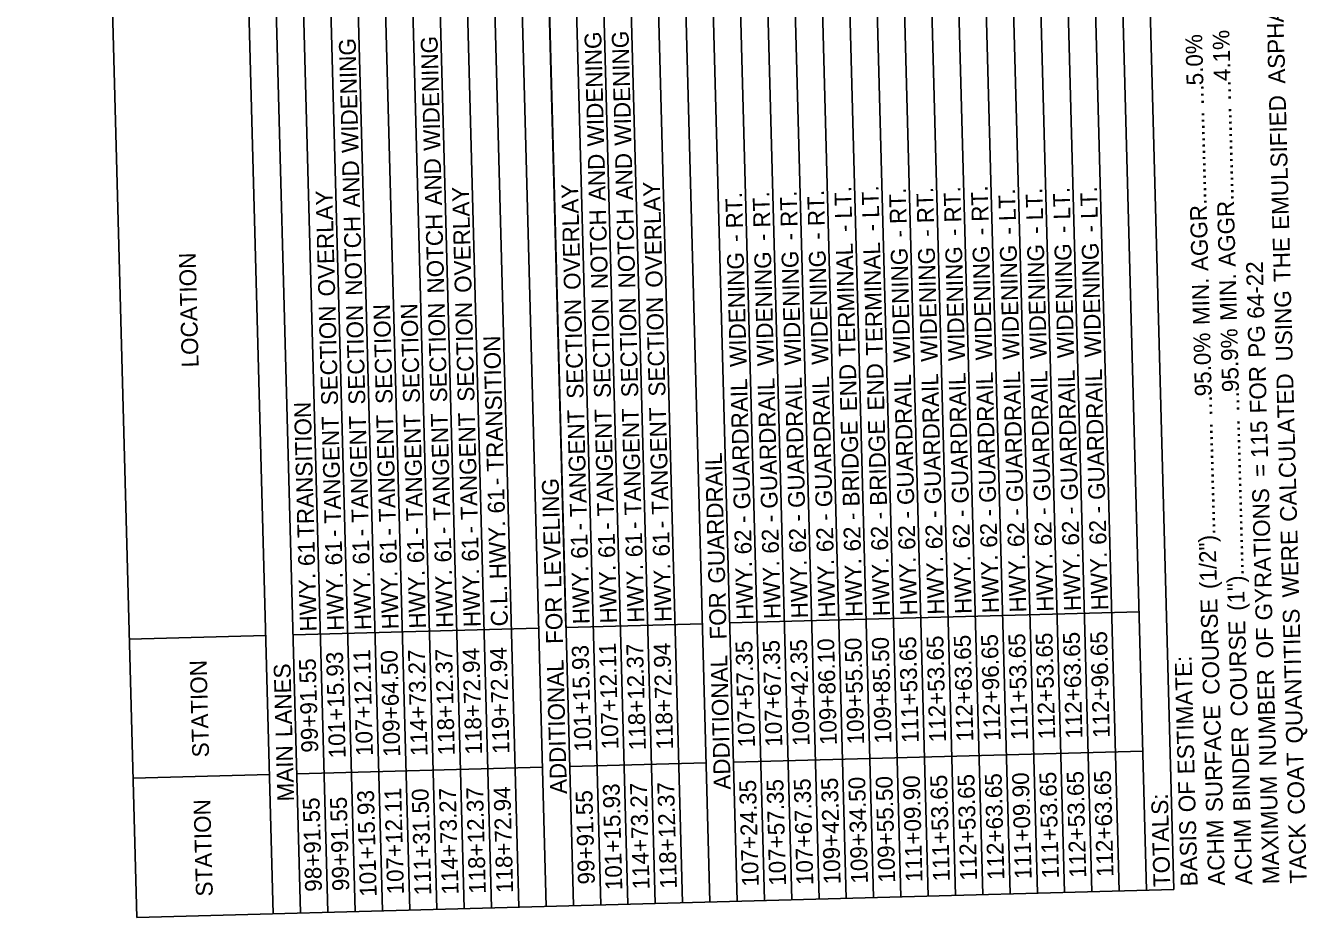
# Model space of a CAD drawing. Extents: x 1930093 to 1931323, y 596452 to 607874.
# Drawn here: x 1930485 to 1930942.8, y 603917.3 to 604235.9 of the extents above; entities that cross this region are included whole.
import ezdxf

# ---------------------------------------------------------------- set-up
doc = ezdxf.new("R2010")
doc.units = 0
doc.layers.add('Default', color=7, linetype='Continuous')

msp = doc.modelspace()

# ---------------------------------------------------------------- linework, layer by layer
at = {"layer": 'Default'}
for p, q in [((1930778.09, 603924.1), (1930738.4, 605402.65)), ((1930787.84, 603924.37), (1930748.15, 605402.91)), ((1930797.58, 603924.63), (1930757.89, 605403.17)), ((1930807.33, 603924.89), (1930767.64, 605403.43)), ((1930817.08, 603925.15), (1930777.39, 605403.69)), ((1930826.82, 603925.41), (1930787.13, 605403.95)), ((1930836.57, 603925.67), (1930796.88, 605404.22)), ((1930846.32, 603925.93), (1930806.63, 605404.48)), ((1930856.06, 603926.2), (1930816.37, 605404.74)), ((1930865.81, 603926.46), (1930826.12, 605405)), ((1930875.55, 603926.72), (1930835.86, 605405.26)), ((1930885.3, 603926.98), (1930845.61, 605405.52)), ((1930895.05, 603927.24), (1930855.36, 605405.79)), ((1930612.4, 603919.66), (1930572.71, 605398.2)), ((1930622.15, 603919.92), (1930582.46, 605398.46)), ((1930631.89, 603920.18), (1930592.2, 605398.72)), ((1930641.64, 603920.44), (1930601.95, 605398.98)), ((1930651.39, 603920.7), (1930611.7, 605399.24)), ((1930661.13, 603920.96), (1930621.44, 605399.51)), ((1930670.88, 603921.23), (1930631.19, 605399.77)), ((1930680.63, 603921.49), (1930640.93, 605400.03)), ((1930690.37, 603921.75), (1930650.68, 605400.29)), ((1930700.12, 603922.01), (1930660.43, 605400.55)), ((1930709.86, 603922.27), (1930670.17, 605400.81)), ((1930719.61, 603922.53), (1930679.92, 605401.08)), ((1930729.36, 603922.8), (1930689.67, 605401.34)), ((1930729.36, 603922.8), (1930689.67, 605401.34)), ((1930739.1, 603923.06), (1930699.41, 605401.6)), ((1930748.85, 603923.32), (1930709.16, 605401.86)), ((1930758.6, 603923.58), (1930718.91, 605402.12)), ((1930768.34, 603923.84), (1930728.65, 605402.38)), ((1930524.68, 603917.3), (1930484.99, 605395.84)), ((1930573.41, 603918.61), (1930533.72, 605397.15)), ((1930583.16, 603918.87), (1930543.47, 605397.41)), ((1930592.91, 603919.13), (1930553.22, 605397.67)), ((1930602.65, 603919.39), (1930562.96, 605397.94)), ((1930670.88, 603921.23), (1930656.54, 604455.33)), ((1930677.96, 604020.9), (1930671.62, 604256.77)), ((1930882.63, 604026.4), (1930736.44, 604022.47)), ((1930882.63, 604026.4), (1930736.44, 604022.47)), ((1930668.21, 604020.64), (1930580.49, 604018.28)), ((1930668.21, 604020.64), (1930580.49, 604018.28)), ((1930726.69, 604022.21), (1930677.96, 604020.9)), ((1930726.69, 604022.21), (1930677.96, 604020.9)), ((1930570.75, 604018.02), (1930522.01, 604016.72)), ((1930883.97, 603976.69), (1930737.77, 603972.76)), ((1930883.97, 603976.69), (1930737.77, 603972.76)), ((1930669.54, 603970.93), (1930581.83, 603968.58)), ((1930669.54, 603970.93), (1930581.83, 603968.58)), ((1930728.02, 603972.5), (1930679.29, 603971.19)), ((1930728.02, 603972.5), (1930679.29, 603971.19)), ((1930572.08, 603968.32), (1930523.35, 603967.01)), ((1930895.05, 603927.24), (1930524.68, 603917.3)), ((1930895.05, 603927.24), (1930524.68, 603917.3))]:
    msp.add_line(p, q, dxfattribs=at)

# ---------------------------------------------------------------- texts
for s, p in [(' ASPHALT', (1930934.95, 604212.93)), (' WIDENING', (1930603.99, 604188.24)), (' WIDENING', (1930633.23, 604189.02)), (' WIDENING', (1930691.71, 604190.59)), (' WIDENING', (1930701.45, 604190.86)), ('5.0%', (1930905.64, 604214.59)), ('4.1%', (1930915.35, 604216.1)), ('…', (1930905.84, 604207.19)), ('…', (1930915.55, 604208.71)), (' EMULSIFIED', (1930936.35, 604160.76)), (' AGGR...............', (1930907.48, 604146.01)), (' AGGR...............', (1930917.19, 604147.53)), (' AND', (1930692.23, 604171.02)), (' AND', (1930701.98, 604171.28)), (' AND', (1930604.51, 604168.66)), (' AND', (1930633.75, 604169.45)), (' OVERLAY', (1930595.61, 604136.96)), (' OVERLAY', (1930644.35, 604138.26)), (' OVERLAY', (1930683.33, 604139.31)), (' OVERLAY', (1930712.57, 604140.09)), (' RT.', (1930751.01, 604161.55)), (' RT.', (1930760.75, 604161.81)), (' RT.', (1930770.5, 604162.08)), (' LT.', (1930780.18, 604164.77)), (' LT.', (1930789.93, 604165.03)), (' RT.', (1930799.74, 604162.86)), (' RT.', (1930809.49, 604163.12)), (' RT.', (1930819.23, 604163.38)), (' RT.', (1930828.98, 604163.65)), (' LT.', (1930838.73, 604163.91)), (' LT.', (1930848.47, 604164.17)), (' LT.', (1930858.22, 604164.43)), (' LT.', (1930867.97, 604164.69)), (' RT.', (1930741.26, 604161.29)), (' NOTCH', (1930605.36, 604137.22)), (' NOTCH', (1930634.6, 604138)), (' NOTCH', (1930693.08, 604139.57)), (' NOTCH', (1930702.82, 604139.83)), (' -', (1930780.31, 604159.92)), (' -', (1930790.06, 604160.18)), (' -', (1930799.87, 604158.01)), (' -', (1930809.62, 604158.27)), (' -', (1930819.36, 604158.53)), (' -', (1930829.11, 604158.79)), (' -', (1930838.86, 604159.05)), (' -', (1930848.6, 604159.31)), (' -', (1930858.35, 604159.58)), (' -', (1930868.1, 604159.84)), (' -', (1930741.39, 604156.44)), (' -', (1930751.14, 604156.7)), (' -', (1930760.89, 604156.96)), (' -', (1930770.63, 604157.22)), (' TERMINAL', (1930781.5, 604115.51)), (' TERMINAL', (1930791.25, 604115.77)), (' WIDENING', (1930859.55, 604114.94)), (' WIDENING', (1930869.29, 604115.21)), (' THE', (1930936.85, 604142.12)), ('LOCATION', (1930546.79, 604113.84)), (' WIDENING', (1930742.59, 604111.8)), (' WIDENING', (1930752.34, 604112.07)), (' WIDENING', (1930762.08, 604112.33)), (' WIDENING', (1930771.83, 604112.59)), (' WIDENING', (1930801.07, 604113.37)), (' WIDENING', (1930810.82, 604113.64)), (' WIDENING', (1930820.56, 604113.9)), (' WIDENING', (1930830.31, 604114.16)), (' WIDENING', (1930840.06, 604114.42)), (' WIDENING', (1930849.8, 604114.68)), (' 64-22', (1930927.45, 604129.01)), (' MIN.', (1930908, 604126.73)), (' MIN.', (1930917.71, 604128.24)), (' USING', (1930937.61, 604113.77)), (' SECTION', (1930596.66, 604098.06)), (' SECTION', (1930606.4, 604098.32)), (' SECTION', (1930616.15, 604098.58)), (' SECTION', (1930625.9, 604098.85)), (' SECTION', (1930635.64, 604099.11)), (' SECTION', (1930645.39, 604099.37)), (' SECTION', (1930684.38, 604100.42)), (' SECTION', (1930694.12, 604100.68)), (' SECTION', (1930703.87, 604100.94)), (' SECTION', (1930713.61, 604101.2)), ('95.0%', (1930908.62, 604103.5)), ('95.9%', (1930918.34, 604105.01)), (' PG', (1930927.82, 604115.1)), (' TRANSITION', (1930655.81, 604074.39)), (' END', (1930782.03, 604095.94)), (' END', (1930791.78, 604096.2)), (' GUARDRAIL', (1930821.93, 604062.97)), (' GUARDRAIL', (1930831.68, 604063.23)), (' GUARDRAIL', (1930841.42, 604063.49)), (' GUARDRAIL', (1930851.17, 604063.76)), (' GUARDRAIL', (1930860.92, 604064.02)), (' GUARDRAIL', (1930870.66, 604064.28)), (' FOR', (1930928.35, 604095.19)), (' GUARDRAIL', (1930743.96, 604060.88)), (' GUARDRAIL', (1930753.7, 604061.14)), (' GUARDRAIL', (1930763.45, 604061.4)), (' GUARDRAIL', (1930773.2, 604061.66)), (' GUARDRAIL', (1930802.44, 604062.45)), (' GUARDRAIL', (1930812.18, 604062.71)), (' CALCULATED', (1930939.15, 604056.47)), ('…', (1930908.82, 604096.1)), ('…', (1930918.53, 604097.61)), (' TRANSITION', (1930588.17, 604050.74)), (' TANGENT', (1930685.51, 604058.21)), (' TANGENT', (1930695.25, 604058.47)), (' TANGENT', (1930705, 604058.73)), (' TANGENT', (1930714.75, 604059)), (' TANGENT', (1930597.79, 604055.86)), (' TANGENT', (1930607.54, 604056.12)), (' TANGENT', (1930617.28, 604056.38)), (' TANGENT', (1930627.03, 604056.64)), (' TANGENT', (1930636.78, 604056.9)), (' TANGENT', (1930646.52, 604057.16)), (' BRIDGE', (1930782.94, 604061.92)), (' BRIDGE', (1930792.69, 604062.19)), (' (1").........................', (1930920.49, 604024.63)), (' 115', (1930928.78, 604079.22)), (' (1/2")..................', (1930910.53, 604032.42)), (' GUARDRAIL', (1930734.92, 604034.39)), (' =', (1930928.96, 604072.47)), (' -', (1930655.94, 604069.53)), (' LEVELING', (1930676.44, 604032.82)), (' 61', (1930656.21, 604059.43)), (' GYRATIONS', (1930930.34, 604021.22)), (' -', (1930783.07, 604057.07)), (' -', (1930792.82, 604057.33)), (' -', (1930802.57, 604057.59)), (' -', (1930812.31, 604057.85)), (' -', (1930822.06, 604058.12)), (' -', (1930831.81, 604058.38)), (' -', (1930841.55, 604058.64)), (' -', (1930851.3, 604058.9)), (' -', (1930861.05, 604059.16)), (' -', (1930870.79, 604059.42)), (' -', (1930646.65, 604052.31)), (' HWY.', (1930656.84, 604035.95)), (' -', (1930685.64, 604053.36)), (' -', (1930695.38, 604053.62)), (' -', (1930705.13, 604053.88)), (' -', (1930714.88, 604054.14)), (' -', (1930744.09, 604056.02)), (' -', (1930753.83, 604056.28)), (' -', (1930763.58, 604056.55)), (' -', (1930773.33, 604056.81)), (' 62', (1930793.12, 604046.13)), (' 62', (1930802.87, 604046.39)), (' 62', (1930812.61, 604046.65)), (' 62', (1930822.36, 604046.92)), (' 62', (1930832.11, 604047.18)), (' 62', (1930841.85, 604047.44)), (' 62', (1930851.6, 604047.7)), (' 62', (1930861.35, 604047.96)), (' 62', (1930871.09, 604048.22)), (' -', (1930597.92, 604051)), (' -', (1930607.67, 604051.26)), (' -', (1930617.41, 604051.52)), (' 61', (1930627.43, 604041.68)), (' -', (1930627.16, 604051.79)), (' 61', (1930637.18, 604041.94)), (' -', (1930636.91, 604052.05)), (' 61', (1930646.92, 604042.21)), (' 61', (1930685.91, 604043.25)), (' 61', (1930695.66, 604043.51)), (' 61', (1930705.4, 604043.78)), (' 61', (1930715.15, 604044.04)), (' 62', (1930744.39, 604044.82)), (' 62', (1930754.13, 604045.08)), (' 62', (1930763.88, 604045.35)), (' 62', (1930773.63, 604045.61)), (' 62', (1930783.37, 604045.87)), (' WERE', (1930939.87, 604029.45)), (' 61', (1930588.44, 604040.64)), (' 61', (1930598.19, 604040.9)), (' 61', (1930607.94, 604041.16)), (' 61', (1930617.68, 604041.42)), ('HWY.', (1930715.72, 604022.89)), ('HWY.', (1930744.96, 604023.68)), ('HWY.', (1930754.7, 604023.94)), ('HWY.', (1930764.45, 604024.2)), ('HWY.', (1930774.2, 604024.46)), ('HWY.', (1930783.94, 604024.72)), ('HWY.', (1930793.69, 604024.98)), ('HWY.', (1930803.44, 604025.24)), ('HWY.', (1930813.18, 604025.51)), ('HWY.', (1930822.93, 604025.77)), ('HWY.', (1930832.67, 604026.03)), ('HWY.', (1930842.42, 604026.29)), ('HWY.', (1930852.17, 604026.55)), ('HWY.', (1930861.91, 604026.81)), ('HWY.', (1930871.66, 604027.08)), ('HWY.', (1930589.01, 604019.49)), ('HWY.', (1930598.76, 604019.75)), ('HWY.', (1930608.51, 604020.01)), ('HWY.', (1930618.25, 604020.27)), ('HWY.', (1930628, 604020.54)), ('HWY.', (1930637.74, 604020.8)), ('HWY.', (1930647.49, 604021.06)), ('HWY.', (1930686.48, 604022.11)), ('HWY.', (1930696.22, 604022.37)), ('HWY.', (1930705.97, 604022.63)), ('C.L.', (1930657.24, 604021.32)), (' FOR', (1930676.97, 604012.84)), (' FOR', (1930735.45, 604014.41)), (' COURSE', (1930911.54, 603994.68)), (' QUANTITIES', (1930941.27, 603977.27)), (' COURSE', (1930921.51, 603986.9)), (' OF', (1930930.7, 604007.64)), ('107+57.35', (1930745.5, 603978.08)), ('107+67.35', (1930755.25, 603978.34)), ('109+42.35', (1930765, 603978.61)), ('109+86.10', (1930774.74, 603978.9)), ('109+55.50', (1930784.49, 603979.16)), ('109+85.50', (1930794.24, 603979.42)), ('111+53.65', (1930803.98, 603979.65)), ('112+53.65', (1930813.73, 603979.91)), ('112+63.65', (1930823.48, 603980.18)), ('112+96.65', (1930833.22, 603980.44)), ('111+53.65', (1930842.97, 603980.7)), ('112+53.65', (1930852.72, 603980.96)), ('112+63.65', (1930862.46, 603981.22)), ('112+96.65', (1930872.21, 603981.48)), ('101+15.93', (1930599.31, 603974.18)), ('107+12.11', (1930609.04, 603975.02)), ('109+64.50', (1930618.8, 603974.72)), ('114+73.27', (1930628.55, 603974.97)), ('118+12.37', (1930638.29, 603975.23)), ('118+72.94', (1930648.04, 603975.5)), ('119+72.94', (1930657.79, 603975.76)), ('101+15.93', (1930687.03, 603976.54)), ('107+12.11', (1930696.76, 603977.38)), ('118+12.37', (1930706.52, 603977.06)), ('118+72.94', (1930716.26, 603977.33)), ('STATION', (1930550.53, 603974.54)), (' LANES', (1930580.33, 603979.54)), ('99+91.55', (1930589.5, 603976.23)), ('ADDITIONAL', (1930678.35, 603961.42)), ('ADDITIONAL', (1930736.83, 603962.99)), (' ESTIMATE:', (1930902.55, 603966.28)), (' NUMBER', (1930931.74, 603969.1)), (' SURFACE', (1930912.67, 603952.75)), (' BINDER', (1930922.42, 603953.02)), ('MAIN', (1930580.89, 603958.8)), (' COAT', (1930941.96, 603951.83)), ('107+24.35', (1930746.84, 603928.38)), ('107+57.35', (1930756.59, 603928.64)), ('107+67.35', (1930766.33, 603928.9)), ('109+42.35', (1930776.08, 603929.16)), ('109+34.50', (1930785.82, 603929.46)), ('109+55.50', (1930795.57, 603929.72)), ('111+09.90', (1930805.32, 603929.98)), ('111+53.65', (1930815.06, 603930.21)), ('112+53.65', (1930824.81, 603930.47)), ('112+63.65', (1930834.56, 603930.73)), ('111+09.90', (1930844.3, 603931.03)), ('111+53.65', (1930854.05, 603931.25)), ('112+53.65', (1930863.8, 603931.51)), ('112+63.65', (1930873.54, 603931.78)), (' OF', (1930902.92, 603952.7)), ('MAXIMUM', (1930932.81, 603929.23)), ('101+15.93', (1930610.39, 603924.73)), ('107+12.11', (1930620.12, 603925.58)), ('111+31.50', (1930629.88, 603925.27)), ('114+73.27', (1930639.63, 603925.52)), ('118+12.37', (1930649.37, 603925.78)), ('118+72.94', (1930659.12, 603926.06)), ('99+91.55', (1930688.3, 603929.13)), ('101+15.93', (1930698.11, 603927.09)), ('114+73.27', (1930707.85, 603927.35)), ('118+12.37', (1930717.6, 603927.61)), ('TOTALS:', (1930893.82, 603928.19)), ('STATION', (1930551.86, 603924.83)), ('98+91.55', (1930590.83, 603926.52)), ('99+91.55', (1930600.58, 603926.78)), ('BASIS', (1930903.57, 603928.45)), ('ACHM', (1930913.32, 603928.71)), ('ACHM', (1930923.06, 603928.97)), ('TACK', (1930942.55, 603929.49))]:
    msp.add_text(s, height=6, rotation=91.5377, dxfattribs=at).set_placement(p)

doc.saveas('drawing.dxf')
